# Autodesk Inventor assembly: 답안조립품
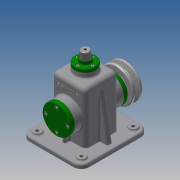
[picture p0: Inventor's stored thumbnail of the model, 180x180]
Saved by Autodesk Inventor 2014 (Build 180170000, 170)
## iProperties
Created: 2015-12
Part Number: 답안조립품
Document SubType Name: Assembly
Designer: Administrator
Author: Administrator
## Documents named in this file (19)
- D:\451225V1021\답안조립품.iam
- D:\451225V1021\1-본체.ipt
- D:\451225V1021\베어링 15 x 35 x 11.ipt
- D:\451225V1021\앞커버.ipt
- D:\451225V1021\뒤커버.ipt
- D:\451225V1021\오일실 15 25 7.ipt
- D:\451225V1021\상부부시.ipt
- D:\451225V1021\와셔.ipt
- D:\451225V1021\멈춤링 15 x 1.ipt
- D:\451225V1021\편심축.ipt
- D:\451225V1021\V-벨트풀리.ipt
- D:\451225V1021\키 5 x 5 x 14.ipt
- D:\451225V1021\고정핀.ipt
- D:\451225V1021\링크.ipt
- D:\451225V1021\슬라이드바.ipt
- D:\451225V1021\멈춤링 6 x 5.ipt
- D:\451225V1021\볼트 M6 x 12.ipt
- D:\451225V1021\볼트 M4 x 10.ipt
- D:\451225V1021\볼트 M3 x 8.ipt
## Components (16 placed, 6 different names)
1. 1-본체:1
2. V-벨트풀리:1
3. 고정핀:1
4. ISO 4018 M6 x 12:1
5. ISO 4762 M4 x 10:1
6. ISO 4762 M4 x 10:2
7. ISO 4762 M4 x 10:3
8. ISO 4762 M4 x 10:4
9. ISO 4762 M4 x 10:5
10. ISO 4762 M4 x 10:6
11. ISO 4762 M4 x 10:7
12. ISO 4762 M4 x 10:8
13. ISO 4762 M3 x 8:1
14. ISO 4762 M3 x 8:2
15. ISO 4762 M3 x 8:3
16. ISO 4762 M3 x 8:4
